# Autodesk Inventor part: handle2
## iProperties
Author: Administrator
Created: 2001-03
Part Number: handle2
Document SubType Name: Modeling
Designer: Administrator
Control State: 0
Master: False
Checked Out: False
PropertySet Name: Design Tracking Control
Shininess: 27.0
PropertySet Name: _Private Model Information
Density: 0.0
Volumn: 0.0
Area: 0.0
PropertySet Name: Model Information
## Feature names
1. Extrusion1
2. Extrusion2
3. Extrusion3
4. Fillet1
5. Fillet2
6. d_cut [Extrusion]
7. Extrusion5
8. Extrusion6
9. Extrusion8
10. Circular Pattern1
